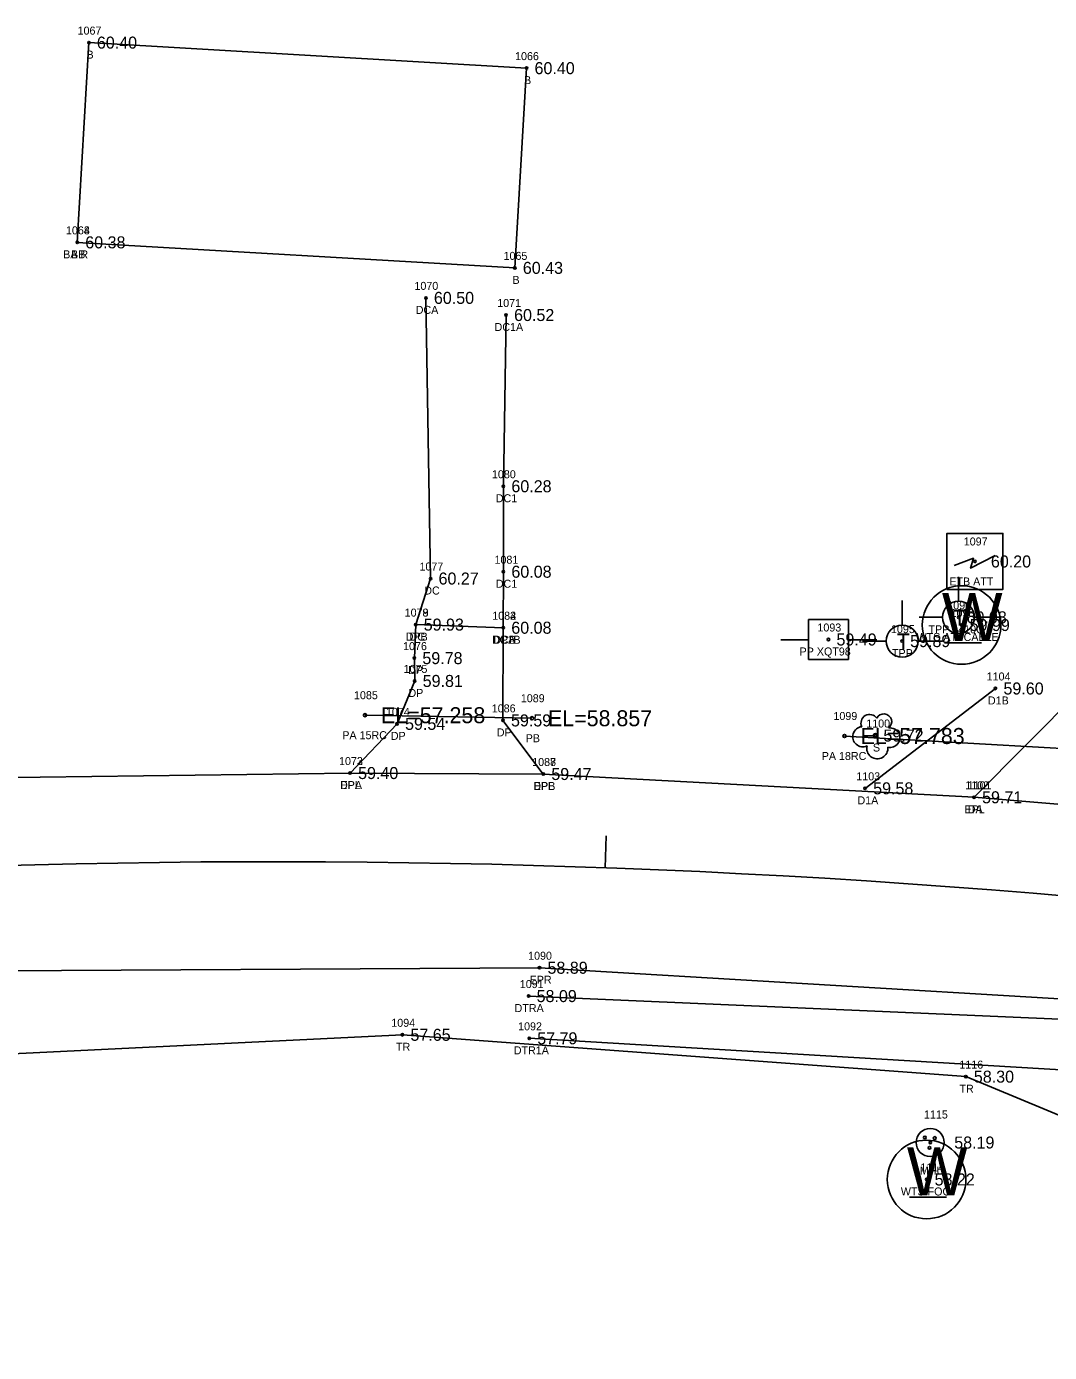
# Model space of a CAD drawing. Extents: x 2420113 to 2422887, y 845323 to 846653.
# Drawn here: x 2420618.3 to 2420746.1, y 845663.2 to 845828.9 of the extents above; entities that cross this region are included whole.
import ezdxf

# ---------------------------------------------------------------- set-up
doc = ezdxf.new("R2010")
doc.units = 0
for name, color, linetype in [('RD_EX_Bldg', 7, 'Continuous'), ('RD_EX_Bldg_txCode', 7, 'Continuous'), ('RD_EX_Conc', 7, 'Continuous'), ('RD_EX_Conc_txCode', 7, 'Continuous'), ('RD_EX_DR_Inlet', 7, 'Continuous'), ('RD_EX_DR_Pipe', 7, 'Continuous'), ('RD_EX_DR_Pipe_txCode', 7, 'Continuous'), ('RD_EX_Driveway', 7, 'Continuous'), ('RD_EX_Driveway_txCode', 7, 'Continuous'), ('RD_EX_H2O', 7, 'Continuous'), ('RD_EX_H2O_txCode', 7, 'Continuous'), ('RD_EX_Road', 7, 'Continuous'), ('RD_EX_Road_txCode', 7, 'Continuous'), ('RD_EX_TX_Bldg_ELEV', 7, 'Continuous'), ('RD_EX_TX_Conc_ELEV', 7, 'Continuous'), ('RD_EX_TX_Driveway_ELEV', 7, 'Continuous'), ('RD_EX_TX_H2O_ELEV', 7, 'Continuous'), ('RD_EX_TX_Road_ELEV', 7, 'Continuous'), ('RD_EX_TX_UT_ELEV', 7, 'Continuous'), ('RD_EX_TX_VEG_ELEV', 7, 'Continuous'), ('RD_EX_UT', 7, 'Continuous'), ('RD_EX_UT_txCode', 7, 'Continuous'), ('RD_EX_VEG', 7, 'Continuous'), ('RD_EX_VEG_txCode', 7, 'Continuous'), ('RD_HC_Cl', 7, 'Continuous'), ('RD_HC_Data_Tic', 7, 'Continuous'), ('RD_HC_Survey_ELEV', 7, 'Continuous'), ('RD_SMD_Locator', 7, 'Continuous'), ('RD_TX_Pipe_ElevEX', 7, 'Continuous')]:
    doc.layers.add(name, color=color, linetype=linetype)

msp = doc.modelspace()

# ---------------------------------------------------------------- linework, layer by layer
at = {"layer": 'RD_EX_Bldg'}
msp.add_lwpolyline([(2420624.64, 845801.91), (2420679.3, 845798.72), (2420680.76, 845823.68), (2420626.09, 845826.87), (2420624.64, 845801.91)], dxfattribs=at)
at = {"layer": 'RD_EX_Conc'}
for points in [[(2420668.19, 845794.97), (2420668.77, 845759.9), (2420666.92, 845754.14), (2420677.86, 845753.75)], [(2420678.21, 845792.83), (2420677.87, 845771.43), (2420677.87, 845760.75), (2420677.86, 845753.75)]]:
    msp.add_lwpolyline(points, dxfattribs=at)
at = {"layer": 'RD_EX_DR_Inlet'}
for centre, radius in [((2420731.19, 845689.42), 1.75), ((2420730.52, 845690.05), 0.175), ((2420731.75, 845689.98), 0.175), ((2420731.1, 845688.75), 0.175)]:
    msp.add_circle(centre, radius, dxfattribs=at)
at = {"layer": 'RD_EX_DR_Pipe'}
for p, q in [((2420660.59, 845742.82), (2420681.44, 845742.44)), ((2420720.48, 845740.22), (2420750.32, 845738.5))]:
    msp.add_line(p, q, dxfattribs=at)
at = {"layer": 'RD_EX_Driveway'}
for p, q in [((2420723.06, 845733.68), (2420739.34, 845746.16)), ((2420736.67, 845732.56), (2420750.24, 845746.27))]:
    msp.add_line(p, q, dxfattribs=at)
for points in [[(2420658.72, 845735.59), (2420664.59, 845741.74), (2420666.79, 845747.1), (2420666.75, 845749.95), (2420666.92, 845754.14)], [(2420677.86, 845753.75), (2420677.82, 845742.17), (2420682.86, 845735.47)]]:
    msp.add_lwpolyline(points, dxfattribs=at)
at = {"layer": 'RD_EX_H2O'}
for points in [[(2420681.02, 845707.72), (2420749.24, 845704.74), (2420794.5, 845700.07), (2420899.98, 845690.96), (2421017.54, 845678.31), (2421112.89, 845668.07), (2421174.6, 845666.39), (2421234.64, 845664.08), (2421293.38, 845665.28), (2421351.67, 845667.88), (2421422.34, 845677.35), (2421426.88, 845673.47), (2421424.22, 845667.22)], [(2420681.1, 845702.44), (2420748.92, 845698.41), (2420794.23, 845693.69), (2420899.45, 845684.25), (2421017.43, 845671.31), (2421111.87, 845660.39), (2421174.2, 845656.63), (2421235.06, 845654.38), (2421294.9, 845653.67), (2421353.19, 845655.89), (2421424.22, 845667.22)]]:
    msp.add_lwpolyline(points, dxfattribs=at)
at = {"layer": 'RD_EX_Road'}
for points in [[(2420388.28, 845680.39), (2420441.29, 845692.04), (2420492.62, 845700.7), (2420553.92, 845707.41), (2420607.69, 845710.85), (2420682.38, 845711.26), (2420749.44, 845707.27), (2420795.12, 845703.44), (2420900.28, 845693.42), (2421017.17, 845682.19), (2421113.9, 845672.97), (2421174.87, 845668.16), (2421234.59, 845666.13), (2421293, 845667.25), (2421351.24, 845671.5), (2421419.82, 845681.17), (2421463.19, 845688.63), (2421558.82, 845713.18), (2421614.57, 845730.45), (2421670.73, 845751.42), (2421735.61, 845780.5), (2421750.75, 845787.87), (2421744.67, 845798.22), (2421739.21, 845808.11)], [(2420376.35, 845701.93), (2420403.68, 845709.11), (2420436.45, 845715.41), (2420465.85, 845720.8), (2420487.58, 845724.76), (2420551.29, 845731.53), (2420607.05, 845734.89), (2420658.72, 845735.59), (2420682.86, 845735.47), (2420736.67, 845732.56), (2420795.4, 845727.65), (2420889.7, 845718.98), (2420911.08, 845716.87), (2420953.91, 845713.71), (2420998.34, 845708.25), (2421018.47, 845706.55), (2421116.02, 845696.98), (2421176.98, 845692), (2421235.85, 845690.14), (2421292.32, 845691.44), (2421350.22, 845695.49), (2421412.35, 845704.28)]]:
    msp.add_lwpolyline(points, dxfattribs=at)
at = {"layer": 'RD_EX_UT'}
for p, q in [((2420734.73, 845760.12), (2420734.73, 845757.05)), ((2420727.68, 845757.15), (2420727.68, 845754.08)), ((2420720.98, 845754.79), (2420715.98, 845754.79)), ((2420715.98, 845754.79), (2420715.98, 845749.79)), ((2420720.98, 845749.79), (2420720.98, 845754.79)), ((2420729.8, 845755.06), (2420732.73, 845755.06)), ((2420736.73, 845755.06), (2420739.8, 845755.06)), ((2420712.54, 845752.23), (2420716.01, 845752.23)), ((2420720.9, 845752.23), (2420724.54, 845752.23)), ((2420722.74, 845752.09), (2420725.68, 845752.09)), ((2420729.68, 845752.09), (2420732.74, 845752.09)), ((2420732.98, 845751.88), (2420737.61, 845751.88)), ((2420715.98, 845749.79), (2420720.98, 845749.79)), ((2420728.61, 845682.59), (2420733.24, 845682.59))]:
    msp.add_line(p, q, dxfattribs=at)
msp.add_lwpolyline([(2420733.27, 845758.53), (2420733.27, 845765.53), (2420740.27, 845765.53), (2420740.27, 845758.53)], close=True, dxfattribs=at)
msp.add_lwpolyline([(2420734.16, 845761.53), (2420736.59, 845762.43), (2420736.24, 845761.18), (2420739.29, 845762.77)], dxfattribs=at)
for centre, radius in [((2420735.11, 845754.09), 4.91), ((2420734.73, 845755.05), 2), ((2420727.68, 845752.08), 2), ((2420730.74, 845684.8), 4.91)]:
    msp.add_circle(centre, radius, dxfattribs=at)
at = {"layer": 'RD_EX_VEG'}
msp.add_lwpolyline([(2420391.44, 845659.63), (2420497.12, 845682.87), (2420554.96, 845697.51), (2420665.26, 845702.88), (2420735.64, 845697.65), (2420790.66, 845674.79), (2421018.22, 845655.05), (2421176.12, 845636.22), (2421296.76, 845636.57), (2421411.61, 845653.11), (2421415.24, 845569.55)], dxfattribs=at)
msp.add_circle((2420724.34, 845740.28), 0.25, dxfattribs=at)
for centre, radius, start, end in [((2420723.62, 845741.83), 1.08, 34.9763, 204.756), ((2420725.38, 845741.99), 0.995, 308.7626, 152.0467), ((2420722.77, 845740.13), 1.26, 96.4518, 294.734), ((2420726.18, 845740.01), 1.22, 256.5667, 98.1046), ((2420724.58, 845738.69), 1.32, 166.8827, 5.7589)]:
    msp.add_arc(centre, radius, start, end, dxfattribs=at)
at = {"layer": 'RD_HC_Cl'}
msp.add_arc((2420649.07, 844578.36), 1146.15, 84.46476, 117.6481, dxfattribs=at)
at = {"layer": 'RD_HC_Data_Tic'}
msp.add_line((2420690.59, 845723.75), (2420690.73, 845727.75), dxfattribs=at)
at = {"layer": 'RD_SMD_Locator'}
for centre, radius in [((2420626.09, 845826.87), 0.15), ((2420680.76, 845823.68), 0.15), ((2420624.64, 845801.91), 0.15), ((2420624.64, 845801.91), 0.15), ((2420679.3, 845798.72), 0.15), ((2420668.19, 845794.97), 0.15), ((2420678.21, 845792.83), 0.15), ((2420677.87, 845771.43), 0.15), ((2420736.77, 845762.03), 0.15), ((2420668.77, 845759.9), 0.15), ((2420677.87, 845760.75), 0.15), ((2420734.73, 845755.05), 0.15), ((2420666.92, 845754.14), 0.15), ((2420666.92, 845754.14), 0.15), ((2420677.86, 845753.75), 0.15), ((2420677.86, 845753.75), 0.15), ((2420677.86, 845753.75), 0.15), ((2420735.11, 845754.09), 0.15), ((2420718.48, 845752.28), 0.15), ((2420727.68, 845752.08), 0.15), ((2420666.75, 845749.95), 0.15), ((2420666.79, 845747.1), 0.15), ((2420739.34, 845746.16), 0.15), ((2420660.59, 845742.82), 0.2), ((2420664.59, 845741.74), 0.15), ((2420677.82, 845742.17), 0.15), ((2420681.44, 845742.44), 0.2), ((2420720.48, 845740.22), 0.2), ((2420724.34, 845740.28), 0.15), ((2420658.72, 845735.59), 0.15), ((2420658.72, 845735.59), 0.15), ((2420682.86, 845735.47), 0.15), ((2420682.86, 845735.47), 0.15), ((2420723.06, 845733.68), 0.15), ((2420736.67, 845732.56), 0.15), ((2420736.67, 845732.56), 0.15), ((2420682.38, 845711.26), 0.15), ((2420681.02, 845707.72), 0.15), ((2420665.26, 845702.88), 0.15), ((2420681.1, 845702.44), 0.15), ((2420735.64, 845697.65), 0.15), ((2420731.19, 845689.42), 0.15), ((2420730.74, 845684.8), 0.15)]:
    msp.add_circle(centre, radius, dxfattribs=at)

# ---------------------------------------------------------------- texts
at = {"layer": 'RD_EX_Bldg_txCode'}
for s, p in [('1067', (2420624.68, 845827.87)), ('B', (2420625.79, 845824.87)), ('1066', (2420679.33, 845824.68)), ('B', (2420680.45, 845821.68)), ('1064', (2420623.23, 845802.91)), ('1068', (2420623.23, 845802.91)), ('BA R', (2420622.88, 845799.91)), ('BB', (2420623.86, 845799.91)), ('1065', (2420677.89, 845799.72)), ('B', (2420679, 845796.72))]:
    msp.add_text(s, height=1, dxfattribs=at).set_placement(p)
at = {"layer": 'RD_EX_Conc_txCode'}
for s, p in [('1070', (2420666.76, 845795.97)), ('1071', (2420677.1, 845793.83)), ('DCA', (2420666.92, 845792.97)), ('DC1A', (2420676.77, 845790.83)), ('1080', (2420676.44, 845772.43)), ('DC1', (2420676.92, 845769.43)), ('1081', (2420676.76, 845761.75)), ('1077', (2420667.39, 845760.9)), ('DC1', (2420676.92, 845758.75)), ('DC', (2420667.99, 845757.9)), ('1079', (2420665.54, 845755.14)), ('1082', (2420676.48, 845754.75)), ('1083', (2420676.48, 845754.75)), ('DC', (2420666.14, 845752.14)), ('DC1B', (2420676.45, 845751.75)), ('DCB', (2420676.61, 845751.75))]:
    msp.add_text(s, height=1, dxfattribs=at).set_placement(p)
at = {"layer": 'RD_EX_DR_Pipe_txCode'}
for s, p in [('1085', (2420659.21, 845744.82)), ('1089', (2420680.05, 845744.44)), ('1099', (2420719.1, 845742.22)), ('PA 15RC', (2420657.75, 845739.82)), ('PB', (2420680.66, 845739.44)), ('PA 18RC', (2420717.64, 845737.22))]:
    msp.add_text(s, height=1, dxfattribs=at).set_placement(p)
at = {"layer": 'RD_EX_Driveway_txCode'}
for s, p in [('1078', (2420665.54, 845755.14)), ('1084', (2420676.48, 845754.75)), ('DPB', (2420665.67, 845752.14)), ('DPA', (2420676.6, 845751.75)), ('1076', (2420665.34, 845750.95)), ('1075', (2420665.4, 845748.1)), ('DP', (2420665.97, 845747.95)), ('1104', (2420738.24, 845747.16)), ('DP', (2420666.01, 845745.1)), ('D1B', (2420738.4, 845744.16)), ('1074', (2420663.2, 845742.74)), ('1086', (2420676.42, 845743.17)), ('DP', (2420677.05, 845740.17)), ('DP', (2420663.81, 845739.74)), ('1073', (2420657.34, 845736.59)), ('1087', (2420681.47, 845736.47)), ('DPA', (2420657.46, 845733.59)), ('1103', (2420721.96, 845734.68)), ('1102', (2420735.57, 845733.56)), ('DPB', (2420681.61, 845733.47)), ('D1A', (2420722.1, 845731.68)), ('DA', (2420735.88, 845730.56))]:
    msp.add_text(s, height=1, dxfattribs=at).set_placement(p)
at = {"layer": 'RD_EX_H2O_txCode'}
for s, p in [('1091', (2420679.92, 845708.72)), ('DTRA', (2420679.27, 845705.72)), ('1092', (2420679.71, 845703.44)), ('DTR1A', (2420679.17, 845700.44))]:
    msp.add_text(s, height=1, dxfattribs=at).set_placement(p)
at = {"layer": 'RD_EX_Road_txCode'}
for s, p in [('1072', (2420657.34, 845736.59)), ('1088', (2420681.47, 845736.47)), ('EPL', (2420657.52, 845733.59)), ('1101', (2420735.86, 845733.56)), ('EPL', (2420681.65, 845733.47)), ('EPL', (2420735.47, 845730.56)), ('1090', (2420680.96, 845712.26)), ('EPR', (2420681.15, 845709.26))]:
    msp.add_text(s, height=1, dxfattribs=at).set_placement(p)
at = {"layer": 'RD_EX_TX_Bldg_ELEV'}
for s, p in [('60.40', (2420627.09, 845826.12)), ('60.40', (2420681.76, 845822.93)), ('60.38', (2420625.64, 845801.16)), ('60.38', (2420625.64, 845801.16)), ('60.43', (2420680.3, 845797.97))]:
    msp.add_text(s, height=1.5, dxfattribs=at).set_placement(p)
at = {"layer": 'RD_EX_TX_Conc_ELEV'}
for s, p in [('60.50', (2420669.19, 845794.22)), ('60.52', (2420679.21, 845792.08)), ('60.28', (2420678.87, 845770.68)), ('60.08', (2420678.87, 845760)), ('60.27', (2420669.77, 845759.15)), ('59.93', (2420667.92, 845753.39)), ('60.08', (2420678.86, 845753)), ('60.08', (2420678.86, 845753))]:
    msp.add_text(s, height=1.5, dxfattribs=at).set_placement(p)
at = {"layer": 'RD_EX_TX_Driveway_ELEV'}
for s, p in [('59.93', (2420667.92, 845753.39)), ('60.08', (2420678.86, 845753)), ('59.78', (2420667.75, 845749.2)), ('59.81', (2420667.79, 845746.35)), ('59.60', (2420740.34, 845745.41)), ('59.59', (2420678.82, 845741.42)), ('59.54', (2420665.59, 845740.99)), ('59.40', (2420659.72, 845734.84)), ('59.47', (2420683.86, 845734.72)), ('59.58', (2420724.06, 845732.93)), ('59.71', (2420737.67, 845731.81))]:
    msp.add_text(s, height=1.5, dxfattribs=at).set_placement(p)
at = {"layer": 'RD_EX_TX_H2O_ELEV'}
for s, p in [('58.09', (2420682.02, 845706.97)), ('57.79', (2420682.1, 845701.69))]:
    msp.add_text(s, height=1.5, dxfattribs=at).set_placement(p)
at = {"layer": 'RD_EX_TX_Road_ELEV'}
for s, p in [('59.40', (2420659.72, 845734.84)), ('59.47', (2420683.86, 845734.72)), ('59.71', (2420737.67, 845731.81)), ('58.89', (2420683.38, 845710.51))]:
    msp.add_text(s, height=1.5, dxfattribs=at).set_placement(p)
at = {"layer": 'RD_EX_TX_UT_ELEV'}
for s, p in [('60.20', (2420738.77, 845761.28)), ('60.08', (2420735.73, 845754.3)), ('59.99', (2420736.11, 845753.34)), ('59.89', (2420728.68, 845751.33)), ('58.19', (2420734.19, 845688.67)), ('58.22', (2420731.74, 845684.05))]:
    msp.add_text(s, height=1.5, dxfattribs=at).set_placement(p)
at = {"layer": 'RD_EX_TX_VEG_ELEV'}
for s, p in [('59.72', (2420725.34, 845739.53)), ('57.65', (2420666.26, 845702.13)), ('58.30', (2420736.64, 845696.9))]:
    msp.add_text(s, height=1.5, dxfattribs=at).set_placement(p)
at = {"layer": 'RD_EX_UT'}
for s, height, p in [('W', 6, (2420732.65, 845752.08)), ('T', 2, (2420734.06, 845754)), ('T', 2, (2420727.01, 845751.03)), ('W', 6, (2420728.27, 845682.8))]:
    msp.add_text(s, height=height, dxfattribs=at).set_placement(p)
at = {"layer": 'RD_EX_UT_txCode'}
for s, p in [('1097', (2420735.38, 845764.03)), ('ETB ATT', (2420733.58, 845759.03)), ('1096', (2420733.32, 845756.05)), ('1098', (2420733.73, 845755.09)), ('1093', (2420717.1, 845753.28)), ('1095', (2420726.29, 845753.08)), ('WTS ATTCABLE', (2420729.49, 845752.09)), ('TPP 4410C', (2420730.97, 845753.05)), ('PP XQT98', (2420714.87, 845750.28)), ('TPP', (2420726.41, 845750.08)), ('1115', (2420730.41, 845692.42)), ('1114', (2420729.96, 845685.8)), ('MHU', (2420729.89, 845685.42)), ('WTS FOC', (2420727.52, 845682.8))]:
    msp.add_text(s, height=1, dxfattribs=at).set_placement(p)
at = {"layer": 'RD_EX_VEG_txCode'}
for s, p in [('1100', (2420723.2, 845741.28)), ('S', (2420724.03, 845738.28)), ('1094', (2420663.87, 845703.88)), ('TR', (2420664.46, 845700.88)), ('1116', (2420734.83, 845698.65)), ('TR', (2420734.84, 845695.65))]:
    msp.add_text(s, height=1, dxfattribs=at).set_placement(p)
at = {"layer": 'RD_HC_Survey_ELEV'}
msp.add_text('59.49', height=1.5, dxfattribs=at).set_placement((2420719.48, 845751.53))
at = {"layer": 'RD_TX_Pipe_ElevEX'}
for s, p in [('EL=57.258', (2420662.59, 845741.82)), ('EL=58.857', (2420683.44, 845741.44)), ('EL=57.783', (2420722.48, 845739.22))]:
    msp.add_text(s, height=2, dxfattribs=at).set_placement(p)

doc.saveas('drawing.dxf')
